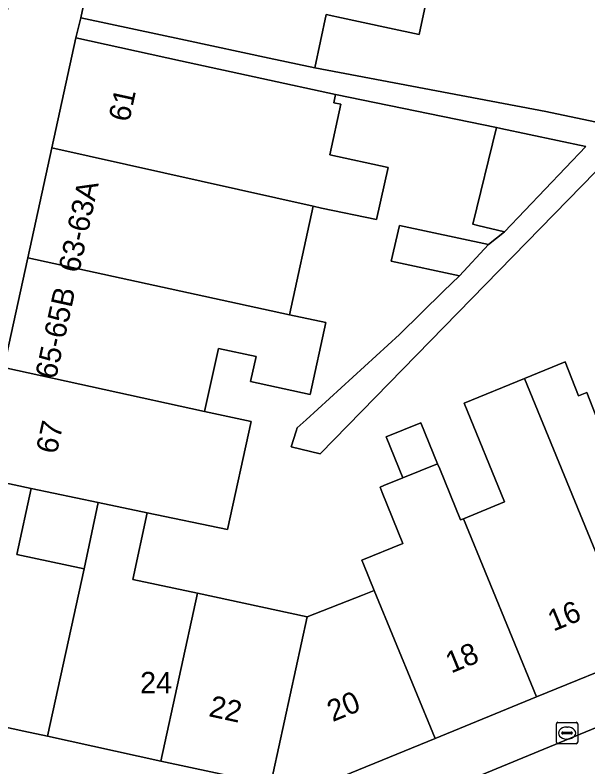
# Model space of a CAD drawing. Extents: x 160856 to 161310, y 384024 to 384878.
# Drawn here: x 161153.45 to 161180.17, y 384750.28 to 384785.38 of the extents above; entities that cross this region are included whole.
import ezdxf

# ---------------------------------------------------------------- set-up
doc = ezdxf.new("R2010")
doc.units = 0
for name, color, linetype in [('IMGEO_Brandkraan', 7, 'Continuous'), ('IMGEO_Erf', 7, 'Continuous'), ('IMGEO_Pand', 7, 'Continuous'), ('IMGEO_Pand_nummerreeks', 7, 'Continuous'), ('IMGEO_Parkeervlak_open', 7, 'Continuous'), ('IMGEO_Voetpad_open', 7, 'Continuous')]:
    doc.layers.add(name, color=color, linetype=linetype)

msp = doc.modelspace()

# ---------------------------------------------------------------- linework, layer by layer
at = {"layer": 'IMGEO_Brandkraan'}
for p, q in [((161178.697, 384751.435), (161178.697, 384752.287)), ((161178.772, 384752.361), (161179.624, 384752.361)), ((161179.185, 384752.141), (161179.21, 384752.141)), ((161179.698, 384752.287), (161179.698, 384751.435)), ((161178.956, 384751.855), (161178.956, 384751.867)), ((161179.394, 384751.818), (161178.996, 384751.818)), ((161178.999, 384751.904), (161179.397, 384751.904)), ((161179.44, 384751.867), (161179.44, 384751.855)), ((161179.624, 384751.361), (161178.772, 384751.361)), ((161179.208, 384751.581), (161179.183, 384751.581))]:
    msp.add_line(p, q, dxfattribs=at)
for points in [[(161178.697, 384751.435), (161178.697, 384752.287)], [(161178.772, 384752.361), (161179.624, 384752.361)], [(161179.698, 384752.287), (161179.698, 384751.435)], [(161179.624, 384751.361), (161178.772, 384751.361)]]:
    msp.add_lwpolyline(points, dxfattribs=at)
for centre, radius, start, end in [((161178.774, 384752.285), 0.0765, 91.552, 178.448), ((161178.774, 384752.285), 0.0765, 91.552, 178.448), ((161179.622, 384752.285), 0.0765, 1.552, 88.448), ((161179.622, 384752.285), 0.0765, 1.552, 88.448), ((161178.996, 384751.864), 0.0403, 85.8775, 175.7526), ((161178.993, 384751.854), 0.0366, 178.938, 274.7102), ((161179.397, 384751.861), 0.043, 264.8664, 352.4533), ((161179.401, 384751.866), 0.0386, 1.7309, 96.639), ((161178.774, 384751.437), 0.0765, 181.552, 268.448), ((161178.774, 384751.437), 0.0765, 181.552, 268.448), ((161179.622, 384751.437), 0.0765, 271.552, 358.448), ((161179.622, 384751.437), 0.0765, 271.552, 358.448)]:
    msp.add_arc(centre, radius, start, end, dxfattribs=at)
for centre, major_axis, ratio, start_param, end_param in [((161179.184, 384751.861), (-0.387, 0.002), 0.722429, 4.712389, 7.853982), ((161179.209, 384751.861), (-0.39, 0.002), 0.717154, 1.570796, 4.712389)]:
    msp.add_ellipse(centre, major_axis=major_axis, ratio=ratio, start_param=start_param, end_param=end_param, dxfattribs=at)
at = {"layer": 'IMGEO_Erf'}
for points in [[(161187.436, 384796.887), (161169.637, 384803.803), (161169.009, 384800.878), (161171.583, 384800.325), (161171.455, 384799.73), (161173.969, 384799.19), (161173.87, 384798.73), (161176.049, 384798.262), (161175.787, 384797.045), (161175.259, 384797.159), (161175.21, 384796.975), (161175.179, 384796.855), (161173.958, 384792.196), (161172.897, 384787.25), (161172.3, 384784.47), (161170.915, 384784.767), (161168.46, 384785.294), (161168.327, 384785.323), (161167.96, 384785.401), (161167.426, 384782.912), (161178.2, 384780.877), (161180.786, 384780.332)], [(161183.088, 384780.69), (161167.686, 384764.893), (161166.327, 384765.221), (161166.562, 384765.947), (161166.616, 384766.114), (161167.026, 384766.488), (161171.385, 384770.467), (161173.434, 384772.491), (161174.177, 384773.209), (161170.989, 384773.888), (161171.377, 384775.55), (161175.537, 384774.661), (161176.286, 384775.253), (161175.029, 384775.558), (161174.807, 384775.611), (161175.901, 384780.135), (161168.404, 384781.666), (161168.321, 384781.286), (161168.652, 384781.214), (161168.137, 384778.858), (161170.847, 384778.267), (161170.679, 384777.498), (161170.315, 384775.832), (161167.748, 384776.367), (161167.36, 384776.454), (161166.255, 384771.388), (161167.943, 384771.02), (161167.213, 384767.671), (161164.437, 384768.276), (161164.69, 384769.437), (161162.936, 384769.819), (161162.294, 384766.878), (161164.457, 384766.406), (161163.355, 384761.362), (161159.617, 384762.14), (161158.948, 384759.032), (161161.955, 384758.385), (161167.068, 384757.285), (161169.65, 384758.3), (161170.206, 384758.519), (161169.706, 384759.74), (161169.626, 384759.931), (161171.545, 384760.715), (161170.574, 384763.095), (161170.475, 384763.338), (161170.657, 384763.412), (161171.534, 384763.77), (161170.753, 384765.685), (161172.378, 384766.348), (161173.159, 384764.433), (161173.258, 384764.19), (161174.229, 384761.81), (161174.362, 384761.864), (161176.285, 384762.648), (161174.401, 384767.265), (161177.209, 384768.411), (161179.113, 384769.188), (161179.73, 384767.599), (161180.125, 384767.752), (161181.312, 384764.694)]]:
    msp.add_lwpolyline(points, dxfattribs=at)
msp.add_lwpolyline([(161157.335, 384762.622), (161154.204, 384763.282), (161153.54, 384760.196), (161156.668, 384759.523)], close=True, dxfattribs=at)
at = {"layer": 'IMGEO_Pand'}
for points in [[(161172.897, 384787.25), (161157.63, 384790.433), (161156.518, 384785.254), (161161.407, 384784.204), (161165.298, 384783.369), (161167.426, 384782.912), (161167.96, 384785.401), (161168.327, 384785.323), (161168.46, 384785.294), (161170.915, 384784.767), (161172.3, 384784.47)], [(161164.963, 384782.417), (161161.167, 384783.246), (161156.282, 384784.312), (161155.162, 384779.18), (161167.36, 384776.454), (161167.748, 384776.367), (161170.315, 384775.832), (161170.679, 384777.498), (161170.847, 384778.267), (161168.137, 384778.858), (161168.652, 384781.214), (161168.321, 384781.286), (161168.404, 384781.666)], [(161175.901, 384780.135), (161174.807, 384775.611), (161175.029, 384775.558), (161176.286, 384775.253), (161180.075, 384779.236), (161176.113, 384780.089)], [(161167.36, 384776.454), (161155.162, 384779.18), (161154.042, 384774.051), (161166.255, 384771.388)], [(161175.537, 384774.661), (161171.377, 384775.55), (161170.989, 384773.888), (161174.177, 384773.209)], [(161167.943, 384771.02), (161166.255, 384771.388), (161154.042, 384774.051), (161152.923, 384768.921), (161162.294, 384766.878), (161162.936, 384769.819), (161164.69, 384769.437), (161164.437, 384768.276), (161167.213, 384767.671)], [(161164.457, 384766.406), (161162.294, 384766.878), (161152.923, 384768.921), (161151.803, 384763.789), (161154.204, 384763.282), (161157.335, 384762.622), (161159.617, 384762.14), (161163.355, 384761.362)], [(161177.209, 384768.411), (161182.508, 384755.488), (161187.243, 384757.429), (161183.861, 384765.675), (161183.736, 384765.635), (161181.312, 384764.694), (161180.125, 384767.752), (161179.73, 384767.599), (161179.113, 384769.188)], [(161174.362, 384761.864), (161177.774, 384753.546), (161182.508, 384755.488), (161177.209, 384768.411), (161174.401, 384767.265), (161176.285, 384762.648)], [(161171.534, 384763.77), (161173.159, 384764.433), (161172.378, 384766.348), (161170.753, 384765.685)], [(161174.362, 384761.864), (161174.229, 384761.81), (161173.258, 384764.19), (161173.159, 384764.433), (161171.534, 384763.77), (161170.657, 384763.412), (161170.475, 384763.338), (161170.574, 384763.095), (161171.545, 384760.715), (161169.626, 384759.931), (161169.706, 384759.74), (161170.206, 384758.519), (161173.04, 384751.605), (161177.774, 384753.546)], [(161154.204, 384763.282), (161151.803, 384763.789), (161149.43, 384752.917), (161153.86, 384751.95), (161154.964, 384751.709), (161156.668, 384759.523), (161153.54, 384760.196)], [(161159.617, 384762.14), (161157.335, 384762.622), (161156.668, 384759.523), (161154.964, 384751.709), (161160.248, 384750.556), (161161.955, 384758.385), (161158.948, 384759.032)], [(161161.955, 384758.385), (161160.248, 384750.556), (161162.793, 384750), (161165.374, 384749.437), (161165.497, 384750), (161167.068, 384757.285)], [(161170.206, 384758.519), (161169.65, 384758.3), (161167.068, 384757.285), (161165.497, 384750), (161165.374, 384749.437), (161166.925, 384749.098), (161169.125, 384750), (161173.04, 384751.605)]]:
    msp.add_lwpolyline(points, close=True, dxfattribs=at)
at = {"layer": 'IMGEO_Parkeervlak_open'}
msp.add_lwpolyline([(161193.977, 384757.662), (161175.435, 384750), (161171.231, 384748.263)], dxfattribs=at)
at = {"layer": 'IMGEO_Voetpad_open'}
msp.add_lwpolyline([(161157.63, 384790.433), (161158.71, 384795.466), (161159.79, 384800.498), (161160.801, 384805.206), (161157.448, 384805.953), (161153.252, 384786.312), (161152.964, 384785.082), (161150.336, 384772.611), (161150.072, 384771.431), (161146.258, 384753.579), (161149.43, 384752.917), (161151.803, 384763.789), (161152.923, 384768.921), (161154.042, 384774.051), (161155.162, 384779.18), (161156.282, 384784.312), (161156.518, 384785.254)], close=True, dxfattribs=at)
for points in [[(161180.786, 384780.332), (161178.2, 384780.877), (161167.426, 384782.912), (161165.298, 384783.369), (161161.407, 384784.204), (161156.518, 384785.254), (161156.282, 384784.312), (161161.167, 384783.246), (161164.963, 384782.417), (161168.404, 384781.666), (161175.901, 384780.135), (161176.113, 384780.089), (161180.075, 384779.236), (161176.286, 384775.253), (161175.537, 384774.661), (161174.177, 384773.209), (161173.434, 384772.491), (161171.385, 384770.467), (161167.026, 384766.488), (161166.616, 384766.114), (161166.562, 384765.947), (161166.327, 384765.221), (161167.686, 384764.893), (161183.088, 384780.69)], [(161171.231, 384748.263), (161175.435, 384750), (161193.977, 384757.662)], [(161182.508, 384755.488), (161177.774, 384753.546), (161173.04, 384751.605), (161169.125, 384750), (161166.925, 384749.098), (161165.374, 384749.437), (161162.793, 384750), (161160.248, 384750.556), (161154.964, 384751.709), (161153.86, 384751.95), (161149.43, 384752.917), (161148.811, 384749.577), (161148.889, 384749.607), (161148.969, 384749.629), (161149.051, 384749.645), (161149.134, 384749.653), (161149.218, 384749.654), (161149.301, 384749.647), (161153.319, 384748.994), (161162.18, 384747.553)]]:
    msp.add_lwpolyline(points, dxfattribs=at)

# ---------------------------------------------------------------- texts
at = {"layer": 'IMGEO_Pand_nummerreeks'}
for s, rotation, p in [('61', 77.6873, (161158.775, 384780.35)), ('63-63A', 77.6816, (161156.438, 384773.305)), ('65-65B', 77.6931, (161155.355, 384768.34)), ('67', 77.6873, (161155.391, 384764.848)), ('16', 22.2973, (161178.558, 384756.592)), ('18', 22.2995, (161173.791, 384754.636)), ('22', 347.6875, (161162.444, 384752.655)), ('20', 22.2938, (161168.265, 384752.37))]:
    msp.add_text(s, height=1, rotation=rotation, dxfattribs=at).set_placement(p)
msp.add_text('24', height=1, dxfattribs=at).set_placement((161159.285, 384753.716))

doc.saveas('drawing.dxf')
